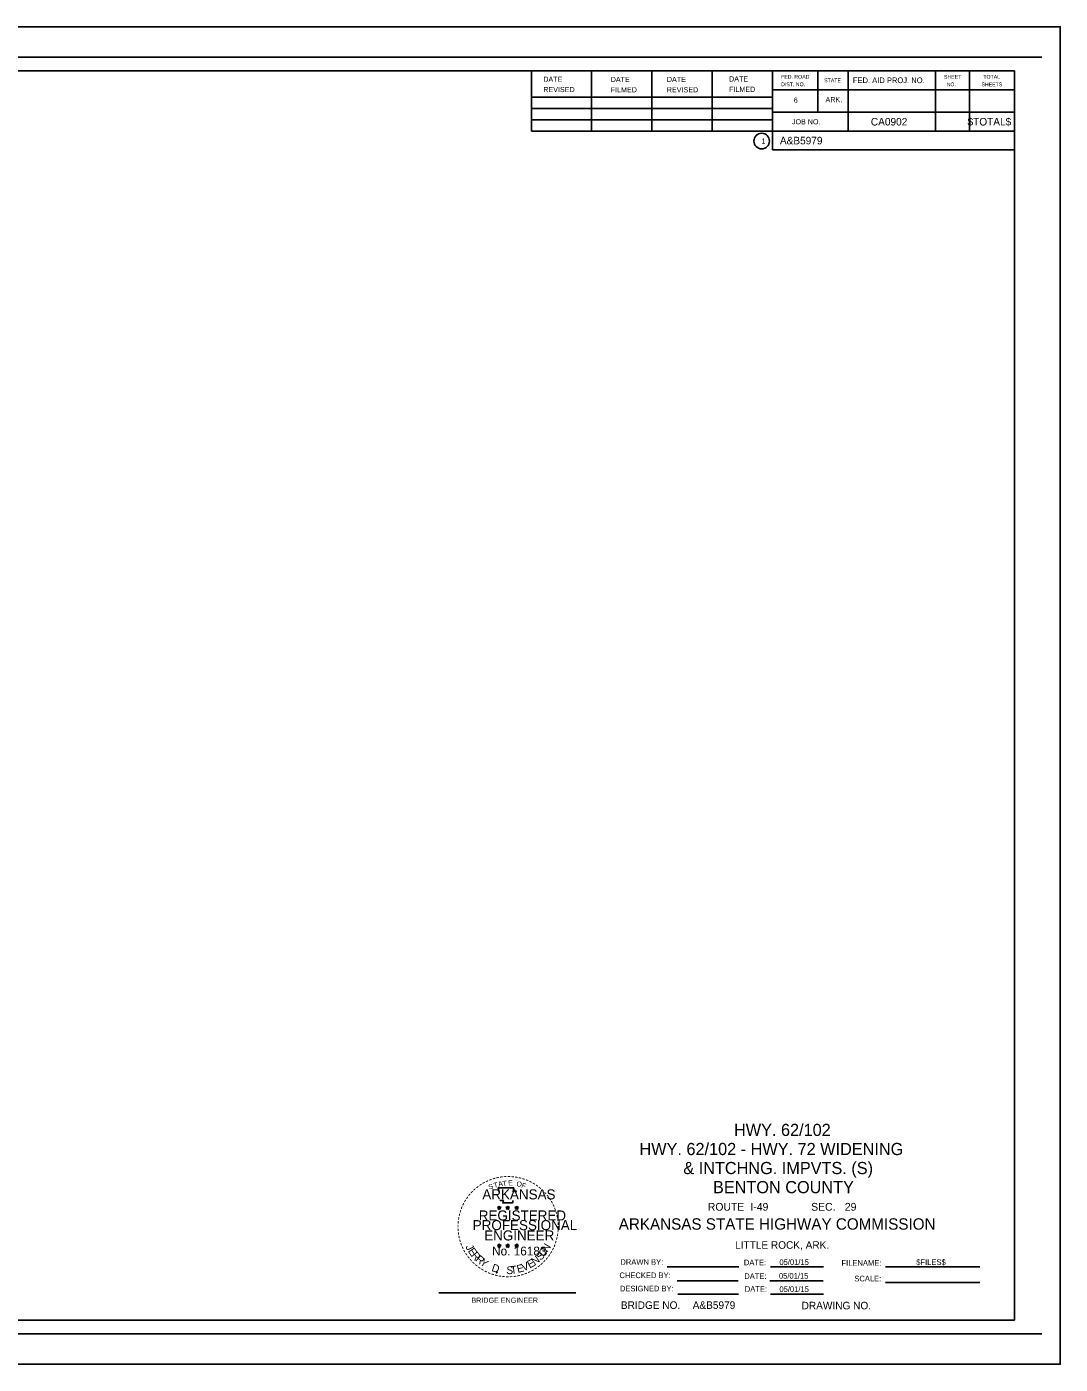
# Model space of a CAD drawing. Extents: x -30250 to -30216, y 5204 to 5226.
# Drawn here: x -30233 to -30216, y 5203.98 to 5225.98 of the extents above; entities that cross this region are included whole.
import ezdxf

# ---------------------------------------------------------------- set-up
doc = ezdxf.new("R2010")
doc.units = 0
for name, color, linetype in [('1', 7, 'Continuous'), ('Bridge_Dims', 7, 'Continuous'), ('S_CONTOUR_MINOR', 7, 'Continuous'), ('S_FENCE', 7, 'Continuous'), ('S_HEADWALL', 7, 'Continuous')]:
    doc.layers.add(name, color=color, linetype=linetype)

msp = doc.modelspace()

# ---------------------------------------------------------------- linework, layer by layer
at = {"layer": '1'}
for p, q in [((-30248.364, 5225.255), (-30216.746, 5225.255)), ((-30224.694, 5225.255), (-30224.694, 5224.264)), ((-30223.704, 5224.264), (-30223.704, 5225.255)), ((-30222.714, 5224.264), (-30222.714, 5225.255)), ((-30221.719, 5224.264), (-30221.719, 5225.255)), ((-30220.728, 5223.954), (-30220.728, 5225.255)), ((-30219.984, 5224.575), (-30219.984, 5225.255)), ((-30219.487, 5224.264), (-30219.487, 5225.255)), ((-30218.046, 5225.255), (-30218.046, 5224.264)), ((-30217.49, 5225.255), (-30217.49, 5224.264)), ((-30216.746, 5204.711), (-30216.746, 5225.255)), ((-30220.732, 5224.821), (-30224.694, 5224.821)), ((-30216.746, 5224.944), (-30220.728, 5224.944)), ((-30220.728, 5224.634), (-30224.694, 5224.634)), ((-30216.746, 5224.575), (-30220.728, 5224.575)), ((-30220.728, 5224.451), (-30224.694, 5224.451)), ((-30216.746, 5224.264), (-30224.694, 5224.264)), ((-30216.746, 5223.954), (-30220.728, 5223.954)), ((-30225.254, 5206.565), (-30225.206, 5206.53)), ((-30225.254, 5206.565), (-30225.195, 5206.565)), ((-30225.224, 5206.586), (-30225.242, 5206.53)), ((-30225.195, 5206.565), (-30225.242, 5206.53)), ((-30225.224, 5206.586), (-30225.206, 5206.53)), ((-30225.115, 5206.565), (-30225.068, 5206.53)), ((-30225.115, 5206.565), (-30225.056, 5206.565)), ((-30225.085, 5206.586), (-30225.104, 5206.53)), ((-30225.056, 5206.565), (-30225.104, 5206.53)), ((-30225.085, 5206.586), (-30225.068, 5206.53)), ((-30224.966, 5206.565), (-30224.919, 5206.53)), ((-30224.966, 5206.565), (-30224.907, 5206.565)), ((-30224.936, 5206.586), (-30224.955, 5206.53)), ((-30224.907, 5206.565), (-30224.955, 5206.53)), ((-30224.936, 5206.586), (-30224.919, 5206.53)), ((-30225.254, 5205.941), (-30225.206, 5205.906)), ((-30225.254, 5205.941), (-30225.195, 5205.941)), ((-30225.224, 5205.962), (-30225.242, 5205.906)), ((-30225.195, 5205.941), (-30225.242, 5205.906)), ((-30225.224, 5205.962), (-30225.206, 5205.906)), ((-30225.115, 5205.941), (-30225.068, 5205.906)), ((-30225.115, 5205.941), (-30225.056, 5205.941)), ((-30225.085, 5205.962), (-30225.104, 5205.906)), ((-30225.056, 5205.941), (-30225.104, 5205.906)), ((-30225.085, 5205.962), (-30225.068, 5205.906)), ((-30224.966, 5205.941), (-30224.919, 5205.906)), ((-30224.966, 5205.941), (-30224.907, 5205.941)), ((-30224.936, 5205.962), (-30224.955, 5205.906)), ((-30224.907, 5205.941), (-30224.955, 5205.906)), ((-30224.936, 5205.962), (-30224.919, 5205.906)), ((-30222.461, 5205.584), (-30221.285, 5205.584)), ((-30220.763, 5205.584), (-30219.888, 5205.584)), ((-30218.869, 5205.584), (-30217.317, 5205.584)), ((-30222.295, 5205.358), (-30221.295, 5205.358)), ((-30220.771, 5205.358), (-30219.896, 5205.358)), ((-30218.869, 5205.327), (-30217.317, 5205.327)), ((-30226.215, 5205.158), (-30223.965, 5205.158)), ((-30222.288, 5205.139), (-30221.288, 5205.139)), ((-30220.763, 5205.139), (-30219.888, 5205.139)), ((-30216.746, 5204.711), (-30248.364, 5204.711))]:
    msp.add_line(p, q, dxfattribs=at)
for points in [[(-30225.244, 5206.884), (-30225.224, 5206.814)], [(-30224.956, 5206.804), (-30224.946, 5206.834), (-30224.996, 5206.824), (-30224.986, 5206.884), (-30225.244, 5206.884)], [(-30225.205, 5206.685), (-30225.205, 5206.675), (-30225.155, 5206.675), (-30225.165, 5206.636), (-30225.006, 5206.636), (-30224.996, 5206.675)]]:
    msp.add_lwpolyline(points, dxfattribs=at)
msp.add_circle((-30225.264, 5205.497), 0.00786, dxfattribs=at)
for centre, radius, start, end in [((-30225.264, 5205.497), 0.00755, 249.7224, 57.042), ((-30225.266, 5205.498), 0.0081, 265.5485, 41.2158)]:
    msp.add_arc(centre, radius, start, end, dxfattribs=at)
msp.add_ellipse((-30220.907, 5224.101), major_axis=(0.128, 0), ratio=0.999873, dxfattribs=at)
at = {"layer": 'Bridge_Dims'}
for p, q in [((-30216.297, 5225.482), (-30249.497, 5225.482)), ((-30249.497, 5204.485), (-30216.297, 5204.485))]:
    msp.add_line(p, q, dxfattribs=at)
msp.add_lwpolyline([(-30249.996, 5225.981), (-30215.996, 5225.981), (-30215.996, 5203.984), (-30249.996, 5203.984)], close=True, dxfattribs=at)

# ---------------------------------------------------------------- texts
at = {"layer": '1'}
for s, height, p in [('DATE', 0.085, (-30224.499, 5225.076)), ('DATE', 0.085, (-30223.39, 5225.072)), ('DATE', 0.085, (-30222.467, 5225.072)), ('DATE', 0.085, (-30221.443, 5225.08)), ('FED. ROAD', 0.062, (-30220.588, 5225.127)), ('DIST. NO.', 0.062, (-30220.588, 5225.003)), ('STATE', 0.062, (-30219.879, 5225.068)), ('FED. AID PROJ. NO.', 0.093, (-30219.407, 5225.054)), ('SHEET', 0.062, (-30217.908, 5225.126)), (' NO.', 0.062, (-30217.889, 5225.002)), ('SHEETS', 0.062, (-30217.292, 5225.002)), ('TOTAL', 0.062, (-30217.261, 5225.126)), ('REVISED', 0.085, (-30224.499, 5224.906)), ('FILMED', 0.085, (-30223.39, 5224.902)), ('REVISED', 0.085, (-30222.467, 5224.902)), ('FILMED', 0.085, (-30221.443, 5224.91)), ('6', 0.085, (-30220.38, 5224.732)), ('ARK.', 0.085, (-30219.857, 5224.74)), ('JOB NO.', 0.085, (-30220.409, 5224.376)), ('CA0902', 0.124, (-30219.111, 5224.357)), ('1', 0.085, (-30220.91, 5224.059)), ('-', 0.132, (-30225.095, 5207.02)), ('ARKANSAS', 0.1652, (-30225.502, 5206.695)), ('ROUTE', 0.128, (-30221.793, 5206.509)), ('I-49', 0.128, (-30221.092, 5206.509)), ('SEC.', 0.128, (-30220.093, 5206.509)), ('29', 0.128, (-30219.539, 5206.509)), ('PROFESSIONAL', 0.16524, (-30225.66, 5206.189)), ('REGISTERED', 0.1652, (-30225.561, 5206.348)), ('ARKANSAS STATE HIGHWAY COMMISSION', 0.187, (-30223.258, 5206.197)), ('ENGINEER', 0.1652, (-30225.472, 5206.02)), ('No. 16183', 0.145, (-30225.342, 5205.773)), ('LITTLE ROCK, ARK.', 0.124, (-30221.345, 5205.883)), ('DRAWN BY:', 0.093, (-30223.231, 5205.619)), ('DATE:', 0.093, (-30221.2, 5205.612)), ('05/01/15', 0.093, (-30220.615, 5205.617)), ('FILENAME:', 0.093, (-30219.594, 5205.603)), ('$FILES$', 0.093, (-30218.364, 5205.617)), ('CHECKED BY:', 0.093, (-30223.247, 5205.4)), ('DATE:', 0.093, (-30221.193, 5205.386)), ('05/01/15', 0.093, (-30220.623, 5205.391)), ('SCALE:', 0.093, (-30219.383, 5205.346)), ('DESIGNED BY:', 0.093, (-30223.239, 5205.182)), ('DATE:', 0.093, (-30221.185, 5205.175)), ('05/01/15', 0.093, (-30220.615, 5205.172)), ('BRIDGE ENGINEER', 0.08499, (-30225.681, 5204.994)), ('BRIDGE NO.', 0.124, (-30223.223, 5204.894)), ('DRAWING NO.', 0.124, (-30220.25, 5204.887))]:
    msp.add_text(s, height=height, dxfattribs=at).set_placement(p)
for s, height, rotation, p in [('-', 0.132, 29.9999, (-30225.48, 5206.908)), ('-', 0.132, 25.7142, (-30225.43, 5206.936)), ('-', 0.132, 21.4285, (-30225.377, 5206.96)), ('-', 0.132, 17.1428, (-30225.323, 5206.981)), ('T', 0.0825, 16.4036, (-30225.304, 5206.884)), ('-', 0.132, 12.8571, (-30225.267, 5206.997)), ('A', 0.0826, 11.2132, (-30225.234, 5206.904)), ('-', 0.132, 8.5714, (-30225.21, 5207.009)), ('T', 0.0826, 6.0228, (-30225.165, 5206.914)), ('-', 0.132, 4.2857, (-30225.153, 5207.017)), ('E', 0.0826, 0.8323, (-30225.075, 5206.924)), ('-', 0.132, 355.7131, (-30225.038, 5207.019)), ('-', 0.132, 351.4274, (-30224.98, 5207.014)), ('O', 0.0825, 350.4515, (-30224.946, 5206.914)), ('-', 0.132, 347.1417, (-30224.923, 5207.004)), ('F', 0.0825, 340.0707, (-30224.867, 5206.894)), ('-', 0.132, 342.856, (-30224.867, 5206.991)), ('-', 0.132, 338.5703, (-30224.811, 5206.974)), ('-', 0.132, 334.2846, (-30224.758, 5206.951)), ('-', 0.132, 329.9989, (-30224.706, 5206.925)), ('-', 0.132, 55.7141, (-30225.727, 5206.668)), ('-', 0.132, 51.4284, (-30225.694, 5206.715)), ('-', 0.132, 47.1427, (-30225.657, 5206.76)), ('-', 0.132, 42.857, (-30225.617, 5206.802)), ('-', 0.132, 38.5713, (-30225.574, 5206.84)), ('-', 0.132, 34.2856, (-30225.528, 5206.876)), ('S', 0.0825, 21.594, (-30225.383, 5206.854)), ('-', 0.132, 325.7132, (-30224.657, 5206.896)), ('-', 0.132, 321.4275, (-30224.61, 5206.863)), ('-', 0.132, 317.1418, (-30224.565, 5206.826)), ('-', 0.132, 312.8561, (-30224.523, 5206.786)), ('-', 0.132, 308.5704, (-30224.485, 5206.743)), ('-', 0.132, 72.8569, (-30225.822, 5206.458)), ('-', 0.132, 68.5712, (-30225.805, 5206.513)), ('-', 0.132, 64.2855, (-30225.782, 5206.567)), ('-', 0.132, 59.9998, (-30225.756, 5206.619)), ('-', 0.132, 304.2847, (-30224.449, 5206.697)), ('-', 0.132, 299.999, (-30224.417, 5206.649)), ('-', 0.132, 295.7133, (-30224.389, 5206.599)), ('-', 0.132, 291.4276, (-30224.365, 5206.546)), ('-', 0.132, 85.714, (-30225.85, 5206.287)), ('-', 0.132, 81.4283, (-30225.845, 5206.345)), ('-', 0.132, 77.1426, (-30225.835, 5206.402)), ('-', 0.132, 287.1419, (-30224.344, 5206.492)), ('-', 0.132, 282.8562, (-30224.328, 5206.436)), ('-', 0.132, 278.5705, (-30224.315, 5206.379)), ('-', 0.132, 274.2848, (-30224.308, 5206.322)), ('-', 0.132, 89.9997, (-30225.851, 5206.229)), ('-', 0.132, 94.2854, (-30225.848, 5206.172)), ('-', 0.132, 98.5711, (-30225.84, 5206.114)), ('-', 0.132, 102.8568, (-30225.828, 5206.058)), ('-', 0.132, 261.4277, (-30224.31, 5206.149)), ('-', 0.132, 265.7134, (-30224.305, 5206.207)), ('-', 0.132, 269.9991, (-30224.305, 5206.264)), ('-', 0.132, 107.1425, (-30225.812, 5206.002)), ('-', 0.132, 111.4282, (-30225.791, 5205.948)), ('-', 0.132, 115.7139, (-30225.767, 5205.895)), ('-', 0.132, 119.9996, (-30225.739, 5205.845)), ('J', 0.127, 296.7753, (-30225.783, 5205.917)), ('E', 0.127, 303.4983, (-30225.745, 5205.846)), ('O', 0.127, 51.0136, (-30224.492, 5205.737)), ('N', 0.127, 59.0798, (-30224.43, 5205.817)), ('-', 0.132, 244.2849, (-30224.374, 5205.927)), ('-', 0.132, 248.5706, (-30224.351, 5205.98)), ('-', 0.132, 252.8563, (-30224.334, 5206.036)), ('-', 0.132, 257.142, (-30224.32, 5206.092)), ('-', 0.132, 124.2853, (-30225.707, 5205.797)), ('-', 0.132, 128.571, (-30225.671, 5205.751)), ('-', 0.132, 132.8567, (-30225.633, 5205.708)), ('R', 0.127, 309.0275, (-30225.693, 5205.771)), ('-', 0.132, 137.1424, (-30225.591, 5205.668)), ('R', 0.127, 318.2612, (-30225.626, 5205.695)), ('Y', 0.127, 325.5438, (-30225.553, 5205.631)), ('V', 0.127, 21.2613, (-30224.827, 5205.511)), ('E', 0.127, 29.1612, (-30224.722, 5205.557)), ('N', 0.127, 37.0638, (-30224.639, 5205.606)), ('S', 0.127, 44.4887, (-30224.545, 5205.682)), ('-', 0.132, 222.8564, (-30224.539, 5205.692)), ('-', 0.132, 227.1421, (-30224.499, 5205.734)), ('-', 0.132, 231.4278, (-30224.462, 5205.779)), ('-', 0.132, 235.7135, (-30224.429, 5205.826)), ('-', 0.132, 239.9992, (-30224.4, 5205.875)), ('-', 0.132, 141.4281, (-30225.546, 5205.631)), ('-', 0.132, 145.7138, (-30225.499, 5205.598)), ('-', 0.132, 149.9995, (-30225.45, 5205.569)), ('-', 0.132, 154.2852, (-30225.398, 5205.543)), ('-', 0.132, 158.5709, (-30225.344, 5205.52)), ('-', 0.132, 162.8566, (-30225.289, 5205.503)), ('D', 0.127, 342.2913, (-30225.359, 5205.519)), ('-', 0.132, 167.1423, (-30225.233, 5205.489)), ('-', 0.132, 171.428, (-30225.176, 5205.479)), ('-', 0.132, 175.7137, (-30225.118, 5205.474)), ('-', 0.132, 179.9994, (-30225.06, 5205.474)), ('S', 0.127, 357.358, (-30225.11, 5205.469)), ('-', 0.132, 184.2851, (-30225.003, 5205.477)), ('T', 0.127, 6.7542, (-30225.03, 5205.469)), ('-', 0.132, 188.5708, (-30224.945, 5205.484)), ('E', 0.127, 14.4797, (-30224.917, 5205.485)), ('-', 0.132, 192.8565, (-30224.889, 5205.497)), ('-', 0.132, 197.1422, (-30224.833, 5205.513)), ('-', 0.132, 201.4279, (-30224.779, 5205.534)), ('-', 0.132, 205.7136, (-30224.726, 5205.558)), ('-', 0.132, 209.9993, (-30224.676, 5205.586)), ('-', 0.132, 214.285, (-30224.628, 5205.618)), ('-', 0.132, 218.5707, (-30224.582, 5205.654))]:
    msp.add_text(s, height=height, rotation=rotation, dxfattribs=at).set_placement(p)
at = {"layer": 'S_CONTOUR_MINOR'}
for s, p in [('HWY. 62/102', (-30221.362, 5207.738)), ('HWY. 62/102 - HWY. 72 WIDENING', (-30222.917, 5207.424)), ('& INTCHNG. IMPVTS. (S)', (-30222.196, 5207.111)), ('BENTON COUNTY', (-30221.708, 5206.797))]:
    msp.add_text(s, height=0.2, dxfattribs=at).set_placement(p)
at = {"layer": 'S_FENCE'}
for p in [(-30220.607, 5224.047), (-30222.042, 5204.894)]:
    msp.add_text('A&B5979', height=0.124, dxfattribs=at).set_placement(p)
at = {"layer": 'S_HEADWALL'}
msp.add_text('$TOTAL$', height=0.124, dxfattribs=at).set_placement((-30217.521, 5224.357))

doc.saveas('drawing.dxf')
